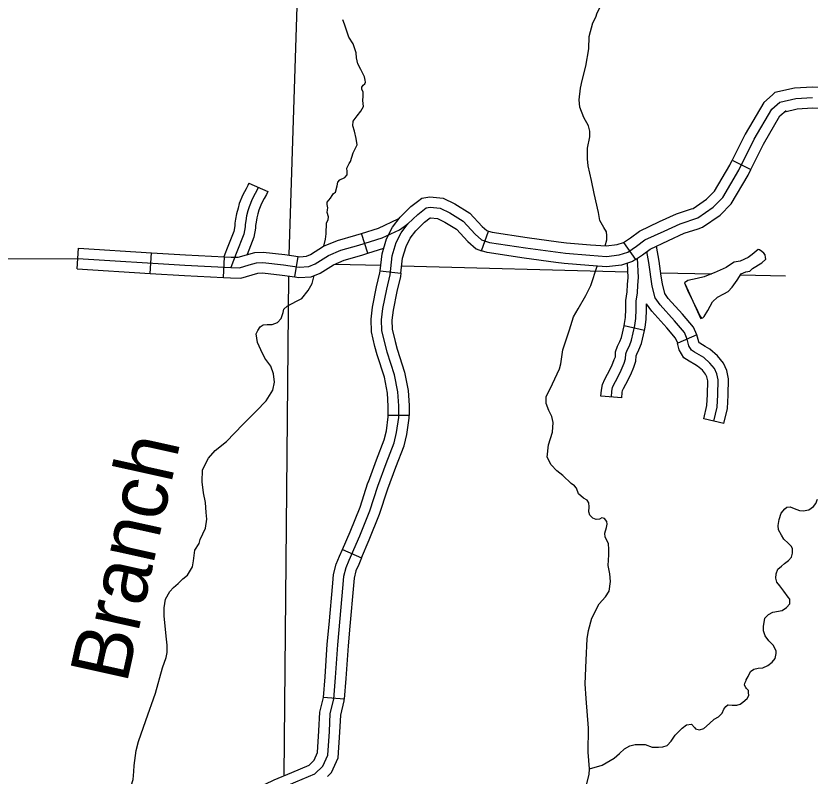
# Model space of a CAD drawing. Extents: x 813775 to 1157140, y 1757555 to 1979907.
# Drawn here: x 919670 to 931113, y 1837175 to 1848131 of the extents above; entities that cross this region are included whole.
import ezdxf

# ---------------------------------------------------------------- set-up
doc = ezdxf.new("R2010")
doc.units = 0
for name, color, linetype in [('Level 31', 7, 'Continuous'), ('Level 32', 7, 'Continuous'), ('Level 35', 7, 'Continuous'), ('Level 4', 7, 'Continuous'), ('Level 45', 7, 'Continuous'), ('Level 5', 7, 'Continuous')]:
    doc.layers.add(name, color=color, linetype=linetype)

msp = doc.modelspace()

# ---------------------------------------------------------------- linework, layer by layer
at = {"layer": 'Level 31'}
for p, q in [((929992, 1846052), (930261, 1845919)), ((926378, 1844747), (926477, 1845030)), ((926477, 1845030), (926477, 1845030)), ((928426, 1844867), (928595, 1844618)), ((924918, 1844458), (925216, 1844424)), ((924843, 1843368), (924843, 1843368)), ((925336, 1842373), (925036, 1842373)), ((924375, 1840439), (924650, 1840321)), ((924400, 1838283), (924101, 1838308)), ((924101, 1838308), (924101, 1838308))]:
    msp.add_line(p, q, dxfattribs=at)
for points in [[(931763, 1847001), (931585, 1847079), (931406, 1847095), (931146, 1847104), (930887, 1847090), (930606, 1847025), (930571, 1846994)], [(930571, 1846994), (930444, 1846882), (930177, 1846425), (929992, 1846052)], [(930748, 1846750), (930929, 1846792), (931149, 1846804), (931387, 1846795), (931510, 1846785), (931642, 1846726)], [(930261, 1845919), (930441, 1846283), (930679, 1846689), (930770, 1846769)], [(929405, 1845349), (929429, 1845356), (929621, 1845487), (929736, 1845606), (929955, 1845977), (929992, 1846052)], [(929500, 1845064), (929563, 1845085), (929815, 1845257), (929976, 1845423), (930219, 1845834), (930261, 1845919)], [(925454, 1845454), (925519, 1845505), (925633, 1845523), (925825, 1845505), (925995, 1845423), (926210, 1845288), (926390, 1845094), (926455, 1845038), (926477, 1845030)], [(924918, 1844458), (924946, 1844702), (925011, 1844918), (925094, 1845084), (925206, 1845232), (925362, 1845383), (925454, 1845454)], [(928426, 1844867), (928526, 1844934), (928655, 1845030), (928945, 1845166), (929188, 1845276), (929405, 1845349)], [(925216, 1844424), (925241, 1844641), (925291, 1844807), (925350, 1844925), (925431, 1845032), (925559, 1845156), (925638, 1845218)], [(925638, 1845218), (925642, 1845221), (925643, 1845221), (925744, 1845212), (925849, 1845160), (926016, 1845055), (926182, 1844877), (926303, 1844773), (926378, 1844747)], [(920561, 1844634), (922105, 1844536), (922767, 1844505), (922891, 1844501), (923033, 1844545), (923135, 1844572), (923228, 1844576), (923526, 1844545), (923752, 1844510), (923890, 1844519), (923983, 1844559), (924174, 1844679), (924352, 1844754), (924609, 1844825), (924947, 1844932), (925195, 1845047), (925318, 1845132)], [(928595, 1844618), (928699, 1844689), (928810, 1844771), (929071, 1844893), (929298, 1844997), (929500, 1845064)], [(926477, 1845030), (926531, 1845012), (927035, 1844938), (927490, 1844875)], [(927490, 1844875), (927603, 1844859), (927949, 1844833), (928174, 1844816), (928332, 1844835), (928422, 1844864), (928426, 1844867)], [(927449, 1844578), (926993, 1844641), (926459, 1844719), (926378, 1844747)], [(928595, 1844618), (928555, 1844591), (928396, 1844540), (928181, 1844515), (927927, 1844533), (927571, 1844560), (927449, 1844578)], [(924843, 1843368), (924793, 1843576), (924788, 1843758), (924807, 1843935), (924867, 1844224), (924914, 1844426), (924918, 1844458)], [(925216, 1844424), (925210, 1844375), (925160, 1844159), (925104, 1843888), (925088, 1843745), (925092, 1843616), (925135, 1843439)], [(925036, 1842373), (925036, 1842507), (925024, 1842692), (924979, 1842922), (924873, 1843244), (924843, 1843368)], [(925135, 1843439), (925162, 1843326), (925270, 1842998), (925322, 1842731), (925336, 1842517), (925336, 1842373)], [(924749, 1841417), (924864, 1841733), (924976, 1842023), (925008, 1842153), (925036, 1842353), (925036, 1842373)], [(925031, 1841314), (925145, 1841627), (925263, 1841933), (925303, 1842096), (925336, 1842332), (925336, 1842373)], [(924375, 1840439), (924484, 1840693), (924628, 1841052), (924743, 1841400), (924749, 1841417)], [(924650, 1840321), (924761, 1840578), (924910, 1840949), (925026, 1841302), (925031, 1841314)], [(924182, 1839361), (924234, 1839953), (924248, 1840080), (924284, 1840230), (924334, 1840344), (924375, 1840439)], [(924650, 1840321), (924609, 1840225), (924570, 1840135), (924544, 1840027), (924532, 1839923), (924481, 1839335)], [(924101, 1838308), (924126, 1838605), (924157, 1839077), (924182, 1839361)], [(924481, 1839335), (924457, 1839054), (924425, 1838583), (924400, 1838283)], [(923950, 1837386), (923969, 1837404), (924017, 1837513), (924037, 1837828), (924051, 1838098), (924101, 1838307), (924101, 1838308)], [(924158, 1837170), (924219, 1837229), (924313, 1837440), (924337, 1837810), (924350, 1838055), (924398, 1838259), (924400, 1838283)], [(923025, 1836895), (923123, 1836992), (923393, 1837120), (923645, 1837228), (923895, 1837333), (923950, 1837386)]]:
    msp.add_lwpolyline(points, dxfattribs=at)
at = {"layer": 'Level 32'}
for p, q in [((923025, 1845718), (923300, 1845598)), ((924740, 1844709), (924649, 1844995)), ((920552, 1844484), (920571, 1844784)), ((921606, 1844418), (921625, 1844717)), ((922663, 1844360), (922677, 1844660)), ((923688, 1844368), (923735, 1844664)), ((928725, 1843598), (928432, 1843663)), ((929481, 1843532), (929205, 1843414)), ((928399, 1842626), (928100, 1842651))]:
    msp.add_line(p, q, dxfattribs=at)
for points in [[(930309, 1846354), (930562, 1846785), (930677, 1846887), (930908, 1846941), (931148, 1846954)], [(925318, 1845132), (925460, 1845270), (925580, 1845363), (925638, 1845372), (925784, 1845359), (925922, 1845292), (926113, 1845172), (926286, 1844985), (926379, 1844905), (926495, 1844865), (927014, 1844790), (927587, 1844710), (927938, 1844683), (928178, 1844665), (928364, 1844687), (928488, 1844727), (928613, 1844812), (928733, 1844901), (929008, 1845030), (929243, 1845136), (929496, 1845221), (929718, 1845372), (929856, 1845514), (930087, 1845905), (930309, 1846354)], [(923025, 1845718), (923011, 1845688), (922986, 1845640), (922938, 1845552), (922887, 1845425), (922870, 1845361), (922846, 1845280), (922836, 1845201), (922826, 1845144), (922824, 1845107), (922809, 1845025), (922705, 1844758), (922690, 1844719)], [(923162, 1845658), (923146, 1845622), (923117, 1845569), (923074, 1845489), (923030, 1845377), (923014, 1845320), (922993, 1845249), (922984, 1845179), (922975, 1845126), (922973, 1845090), (922955, 1844984), (922845, 1844704), (922767, 1844505)], [(923300, 1845598), (923281, 1845556), (923249, 1845497), (923210, 1845425), (923172, 1845329), (923158, 1845279), (923141, 1845219), (923132, 1845156), (923124, 1845109), (923122, 1845072), (923100, 1844944), (923002, 1844692)], [(924649, 1844995), (924892, 1845072), (925178, 1845205)], [(924383, 1839938), (924396, 1840054), (924427, 1840182), (924472, 1840285), (924623, 1840636), (924769, 1841000), (924884, 1841351), (925004, 1841680), (925120, 1841978), (925155, 1842125), (925186, 1842342), (925186, 1842512), (925173, 1842712), (925124, 1842960), (925018, 1843285), (924942, 1843596), (924938, 1843752), (924956, 1843912), (925013, 1844192), (925062, 1844400), (925093, 1844671), (925151, 1844863), (925222, 1845005), (925318, 1845132)], [(923735, 1844664), (923759, 1844660), (923855, 1844667), (923913, 1844692), (924104, 1844812), (924302, 1844896), (924567, 1844969), (924649, 1844995)], [(920571, 1844784), (921625, 1844717)], [(921625, 1844717), (922113, 1844686), (922677, 1844660)], [(922690, 1844719), (922667, 1844660)], [(922677, 1844660), (922773, 1844655), (922871, 1844652), (922992, 1844689), (923112, 1844721), (923233, 1844727), (923545, 1844694), (923735, 1844664)], [(924740, 1844709), (924970, 1844782)], [(929343, 1843473), (929303, 1843566), (929161, 1843735), (928953, 1843966), (928882, 1844068), (928837, 1844237), (928788, 1844575), (928761, 1844735)], [(928968, 1844381), (928936, 1844598), (928900, 1844813)], [(923688, 1844368), (923745, 1844359), (923925, 1844371), (924053, 1844425), (924244, 1844545), (924401, 1844612), (924652, 1844681), (924740, 1844709)], [(928250, 1842638), (928257, 1842720), (928266, 1842775), (928288, 1842828), (928327, 1842894), (928391, 1843024), (928432, 1843125), (928455, 1843186), (928460, 1843259), (928478, 1843314), (928510, 1843378), (928540, 1843455), (928587, 1843669), (928601, 1843768), (928608, 1843900), (928608, 1844019), (928624, 1844138), (928633, 1844250), (928640, 1844359), (928628, 1844641)], [(920552, 1844484), (921606, 1844418)], [(928432, 1843663), (928440, 1843696), (928452, 1843782), (928458, 1843904), (928458, 1844029), (928475, 1844154), (928483, 1844260), (928490, 1844361), (928481, 1844568)], [(921606, 1844418), (922097, 1844387), (922663, 1844360)], [(922663, 1844360), (922760, 1844355), (922911, 1844350), (923074, 1844401), (923158, 1844423), (923224, 1844426), (923506, 1844396), (923688, 1844368)], [(929481, 1843532), (929432, 1843646), (929274, 1843834), (929070, 1844060), (929020, 1844132), (928984, 1844267), (928968, 1844381)], [(928725, 1843598), (928735, 1843643), (928751, 1843753), (928758, 1843896), (928758, 1843983)], [(929205, 1843414), (929174, 1843487), (929048, 1843636), (928835, 1843873), (928758, 1843983)], [(928100, 1842651), (928108, 1842739), (928121, 1842818), (928154, 1842896), (928195, 1842965), (928254, 1843086), (928292, 1843179), (928307, 1843218), (928311, 1843288), (928339, 1843372), (928373, 1843439), (928396, 1843498), (928432, 1843663)], [(928399, 1842626), (928405, 1842702), (928411, 1842732), (928422, 1842760), (928459, 1842823), (928528, 1842963), (928572, 1843070), (928603, 1843155), (928608, 1843231), (928617, 1843257), (928647, 1843318), (928683, 1843411), (928725, 1843598)], [(924200, 1838077), (924249, 1838283), (924276, 1838594), (924307, 1839065), (924383, 1839938)], [(921240, 1834010), (921310, 1834319), (921403, 1834630), (921501, 1834843), (921679, 1835061), (921936, 1835252), (922149, 1835416), (922278, 1835572), (922442, 1835927), (922580, 1836154), (922842, 1836447), (923015, 1836672), (923210, 1836868), (923455, 1836983), (923703, 1837090), (923978, 1837206), (924094, 1837317), (924165, 1837477), (924187, 1837819), (924200, 1838077)]]:
    msp.add_lwpolyline(points, dxfattribs=at)
at = {"layer": 'Level 35'}
for points in [[(927831, 1847198), (927882, 1847404), (927924, 1847656), (927929, 1847833), (927983, 1848031), (928024, 1848112), (928044, 1848175), (928095, 1848266), (928151, 1848332), (928217, 1848408), (928296, 1848464)], [(924692, 1847251), (924638, 1847356), (924597, 1847438), (924576, 1847524), (924573, 1847599), (924527, 1847728), (924467, 1847822), (924405, 1848011), (924382, 1848075)], [(924489, 1846031), (924529, 1846159), (924589, 1846270), (924571, 1846363), (924547, 1846467), (924524, 1846547), (924529, 1846614), (924586, 1846689), (924638, 1846759), (924679, 1846827), (924669, 1846912), (924674, 1846974), (924672, 1847031), (924656, 1847073), (924654, 1847104), (924674, 1847132), (924698, 1847153), (924708, 1847174), (924700, 1847202), (924692, 1847251)], [(927961, 1845756), (927914, 1845972), (927904, 1846070), (927907, 1846222), (927941, 1846388), (927939, 1846469), (927921, 1846547), (927855, 1846664), (927794, 1846814), (927787, 1846919), (927804, 1847088), (927831, 1847198)], [(924108, 1844814), (924132, 1844912), (924142, 1844992), (924145, 1845148), (924170, 1845192), (924176, 1845233), (924157, 1845298), (924160, 1845334), (924165, 1845363), (924157, 1845412), (924155, 1845448), (924201, 1845503), (924227, 1845541), (924248, 1845570), (924276, 1845588), (924297, 1845681), (924310, 1845733), (924338, 1845769), (924411, 1845800), (924445, 1845839), (924445, 1845886), (924439, 1845938), (924473, 1846005), (924489, 1846031)], [(928162, 1844817), (928183, 1844904), (928183, 1844965), (928178, 1845019), (928139, 1845083), (928083, 1845181), (928066, 1845298), (928002, 1845570), (927961, 1845756)], [(929690, 1844413), (929585, 1844372), (929487, 1844345), (929353, 1844315), (929304, 1844284), (929358, 1844154), (929468, 1843934), (929524, 1843809), (929546, 1843772), (929568, 1843777), (929585, 1843797), (929641, 1843885), (929707, 1844010), (929781, 1844078), (929871, 1844127), (929932, 1844159), (929991, 1844220), (930064, 1844323), (930118, 1844413), (930189, 1844443), (930245, 1844453), (930284, 1844489), (930419, 1844572), (930475, 1844626), (930470, 1844651), (930465, 1844685), (930446, 1844712), (930419, 1844736), (930384, 1844761), (930365, 1844763), (930279, 1844692), (930223, 1844648), (930103, 1844594), (930020, 1844582), (929979, 1844558), (929905, 1844506), (929729, 1844426), (929690, 1844413)], [(927521, 1843118), (927552, 1843318), (927645, 1843604), (927706, 1843792), (927770, 1843910), (927880, 1844101), (927956, 1844243), (928047, 1844525)], [(923133, 1843549), (923154, 1843596), (923187, 1843648), (923234, 1843676), (923288, 1843684), (923363, 1843684), (923441, 1843713), (923493, 1843770), (923519, 1843855), (923531, 1843904), (923578, 1843946), (923643, 1843982), (923723, 1844023), (923788, 1844060), (923883, 1844174), (923940, 1844272), (923967, 1844389)], [(929307, 1844276), (929539, 1843766)], [(922940, 1842241), (923131, 1842433), (923275, 1842583), (923371, 1842736), (923394, 1842850), (923381, 1842974), (923345, 1843083), (923257, 1843199), (923198, 1843318), (923151, 1843422), (923133, 1843549)], [(927410, 1842271), (927393, 1842357), (927349, 1842443), (927310, 1842543), (927308, 1842641), (927401, 1842827), (927501, 1843042), (927521, 1843118)], [(922404, 1841116), (922373, 1841257), (922353, 1841415), (922360, 1841591), (922446, 1841756), (922541, 1841868), (922704, 1841997), (922940, 1842241)], [(927672, 1841391), (927552, 1841505), (927462, 1841576), (927384, 1841661), (927325, 1841771), (927342, 1841948), (927401, 1842131), (927410, 1842271)], [(928227, 1840088), (928203, 1840209), (928212, 1840365), (928215, 1840446), (928208, 1840520), (928183, 1840573), (928159, 1840617), (928154, 1840676), (928181, 1840757), (928190, 1840806), (928186, 1840843), (928151, 1840889), (928112, 1840896), (928078, 1840879), (928029, 1840872), (927983, 1840892), (927939, 1840936), (927924, 1840982), (927929, 1841056), (927926, 1841112), (927899, 1841151), (927846, 1841178), (927777, 1841244), (927748, 1841325), (927716, 1841357), (927672, 1841391)], [(930746, 1840237), (930801, 1840282), (930843, 1840331), (930860, 1840387), (930860, 1840448), (930843, 1840482), (930796, 1840534), (930735, 1840590), (930699, 1840646), (930657, 1840725), (930652, 1840788), (930669, 1840874), (930696, 1840965), (930750, 1841028), (930779, 1841050), (930828, 1841055), (930882, 1841033), (930958, 1841001), (931012, 1840996), (931097, 1841011), (931161, 1841062), (931195, 1841102), (931219, 1841165)], [(922144, 1840069), (922215, 1840192), (922231, 1840277), (922239, 1840355), (922249, 1840432), (922309, 1840528), (922327, 1840583), (922404, 1840748), (922420, 1840878), (922412, 1840976), (922404, 1841116)], [(930626, 1838976), (930584, 1839055), (930518, 1839123), (930467, 1839194), (930442, 1839270), (930440, 1839331), (930459, 1839449), (930516, 1839503), (930577, 1839539), (930711, 1839561), (930772, 1839603), (930819, 1839656), (930821, 1839725), (930797, 1839755), (930736, 1839838), (930675, 1839916), (930636, 1839972), (930621, 1840029), (930623, 1840090), (930650, 1840156), (930699, 1840202), (930746, 1840237)], [(921784, 1838737), (921836, 1838883), (921849, 1838956), (921851, 1839064), (921836, 1839191), (921805, 1839484), (921807, 1839600), (921823, 1839724), (921887, 1839833), (921942, 1839893), (922006, 1839950), (922074, 1840020), (922144, 1840069)], [(927873, 1838505), (927887, 1838848), (927902, 1839151), (927922, 1839273), (927966, 1839452), (928076, 1839658), (928166, 1839756), (928217, 1839841), (928237, 1839978), (928227, 1840088)], [(929791, 1838028), (929846, 1838083), (929868, 1838139), (929897, 1838180), (929929, 1838200), (929931, 1838200), (929992, 1838198), (930056, 1838198), (930107, 1838210), (930144, 1838239), (930208, 1838295), (930232, 1838337), (930225, 1838381), (930225, 1838408), (930198, 1838435), (930186, 1838452), (930169, 1838484), (930173, 1838516), (930191, 1838552), (930193, 1838562), (930220, 1838611), (930252, 1838680), (930301, 1838716), (930364, 1838731), (930433, 1838736), (930506, 1838770), (930567, 1838817), (930609, 1838871), (930626, 1838944), (930626, 1838976)], [(921373, 1837326), (921404, 1837546), (921437, 1837673), (921543, 1837976), (921683, 1838370), (921784, 1838737)], [(927931, 1837199), (927936, 1837279), (927917, 1837521), (927922, 1837868), (927885, 1838292), (927873, 1838505)], [(927936, 1837279), (928118, 1837331), (928289, 1837432), (928369, 1837503), (928440, 1837566), (928514, 1837610), (928592, 1837632), (928736, 1837632), (928839, 1837593), (928929, 1837593), (928993, 1837596), (929054, 1837618), (929113, 1837676), (929169, 1837767), (929272, 1837865), (929330, 1837914), (929406, 1837923), (929445, 1837877), (929460, 1837855), (929521, 1837843), (929580, 1837862), (929665, 1837933), (929731, 1837997), (929791, 1838028)], [(920789, 1836253), (920871, 1836365), (920949, 1836458), (921049, 1836544), (921168, 1836715), (921295, 1836927), (921360, 1837126), (921370, 1837240), (921373, 1837326)], [(927812, 1836528), (927829, 1836800), (927890, 1837050), (927931, 1837199)]]:
    msp.add_lwpolyline(points, dxfattribs=at)
at = {"layer": 'Level 4'}
for points in [[(923893, 1853611), (923862, 1852749), (923602, 1844685)], [(923599, 1844382), (923530, 1837179)]]:
    msp.add_lwpolyline(points, dxfattribs=at)
at = {"layer": 'Level 45'}
msp.add_line((929872, 1842256), (929580, 1842326), dxfattribs=at)
for points in [[(929726, 1842291), (929774, 1842492), (929783, 1842670), (929788, 1842885), (929770, 1842974), (929735, 1843047), (929669, 1843127), (929580, 1843207), (929448, 1843285), (929404, 1843312), (929368, 1843376), (929343, 1843473)], [(929603, 1843367), (929526, 1843413), (929516, 1843419), (929508, 1843433), (929483, 1843533)], [(929452, 1843109), (929370, 1843157), (929293, 1843205), (929228, 1843319), (929204, 1843413)], [(929872, 1842256), (929923, 1842471), (929933, 1842665), (929938, 1842899), (929913, 1843022), (929863, 1843128), (929778, 1843231), (929669, 1843329), (929603, 1843367)], [(929580, 1842326), (929625, 1842514), (929633, 1842676), (929638, 1842871), (929626, 1842927), (929608, 1842966), (929561, 1843023), (929491, 1843085), (929452, 1843109)]]:
    msp.add_lwpolyline(points, dxfattribs=at)
at = {"layer": 'Level 5'}
for points in [[(912972, 1844659), (920561, 1844630)], [(924264, 1844554), (924927, 1844536)], [(925228, 1844529), (928486, 1844443)], [(928961, 1844430), (929697, 1844411)], [(930110, 1844400), (930757, 1844383)]]:
    msp.add_lwpolyline(points, dxfattribs=at)

# ---------------------------------------------------------------- texts
at = {"layer": 'Level 35'}
msp.add_text('Branch', height=844.8, rotation=77.4825, dxfattribs=at).set_placement((921266, 1838495))

doc.saveas('drawing.dxf')
